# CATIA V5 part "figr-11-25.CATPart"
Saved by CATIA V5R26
Part number: Part1
Bounding box of the stored display mesh (mm): x -89.703 to 75.958, y -127.286 to 108.862, z -26.487 to 19.815
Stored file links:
  D:\_Deepak\CATIA\CATIA V5-6R2016_Deepak\Resources\Part files\Partfiles\c11_catia_v5_6r2016_prt\figr-11-25.CATPart
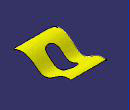
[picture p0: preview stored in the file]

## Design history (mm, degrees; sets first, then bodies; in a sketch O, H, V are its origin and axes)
Set1
  Extrude1: Element1 Sketch3, Lim1 86, Lim2 94, Direction yz-plane
  Sketch1 on xy-plane, origin (0, 0, 0), H (1, 0, 0), V (0, 1, 0)
    line L1 (64.3059, 108.8616) -> (75.9293, -106.0218)
    arc A1 centre (55.7837, -107.1115) radius 20.175 from (75.9293, -106.0218) to (55.7837, -127.2865) cw
    line L2 (55.7837, -127.2865) -> (-64.7868, -127.2865)
    arc A2 centre (-64.7868, -102.3613) radius 24.9252 from (-64.7868, -127.2865) to (-89.6873, -101.2501) cw
    line L3 (-89.6873, -101.2501) -> (-80.3115, 108.8616)
    line L4 (-80.3115, 108.8616) -> (64.3059, 108.8616)
    tangency: A1 L1, A2 L2, A2 L3, A1 L2
    horizontal: L2 H, L4 H
  Extrude2: Element1 Sketch1, Lim1 86, Lim2 94, Direction xy-plane
  Split1: ToCut Extrude1, Cutting Extrude2
  Sketch2 on xy-plane, origin (0, 0, 0), H (1, 0, 0), V (0, 1, 0)
    construction line L1 (-11.3849, 28.4134) -> (-11.3849, -36.9379)
    line L2 (12.8382, 28.4134) -> (12.8382, -36.9379)
    line L3 (-35.608, -36.9379) -> (-35.608, 28.4134)
    arc A1 centre (-11.3849, -36.9379) radius 24.2231 from (12.8382, -36.9379) to (-35.608, -36.9379) cw
    arc A2 centre (-11.3849, 28.4134) radius 24.2231 from (-35.608, 28.4134) to (12.8382, 28.4134) cw
    vertical: L1 V
    tangency: A1 L2, A2 L2, A1 L3, A2 L3
    parallelism: L1 L2
  Extrude3: Element1 Sketch2, Lim1 86, Lim2 94, Direction xy-plane
  Split2: ToCut Split1, Cutting Extrude3
  Boundary1: Boundary edge of Split2, Support Split2
Body1 (main body)
  Sketch3 on yz-plane, origin (0, 0, 0), H (0, 1, 0), V (0, 0, 1)
    spline S1 through (-130.9721, 0) (-85.5087, 19.8151) (-38.0512, 0) (0, -25.6483) (60.0541, -1.7202) (134.7951, -4.3868)
    point P1 (-130.9721, 0)
    point P2 (-38.0512, 0)
    point P3 (0, -25.6483)
    coincidence: P1 H, P2 H, P3 V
